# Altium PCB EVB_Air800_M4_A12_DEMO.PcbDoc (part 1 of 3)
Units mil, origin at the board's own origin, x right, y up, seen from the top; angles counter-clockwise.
Board outline 2106 x 2583.39 mil, 2 copper layers (Top, Bottom), stack 12.7 mil thick; 125 components, 94 nets, 414 pads, 454 vias.
Unrouted connection lines stored in the file: 290.
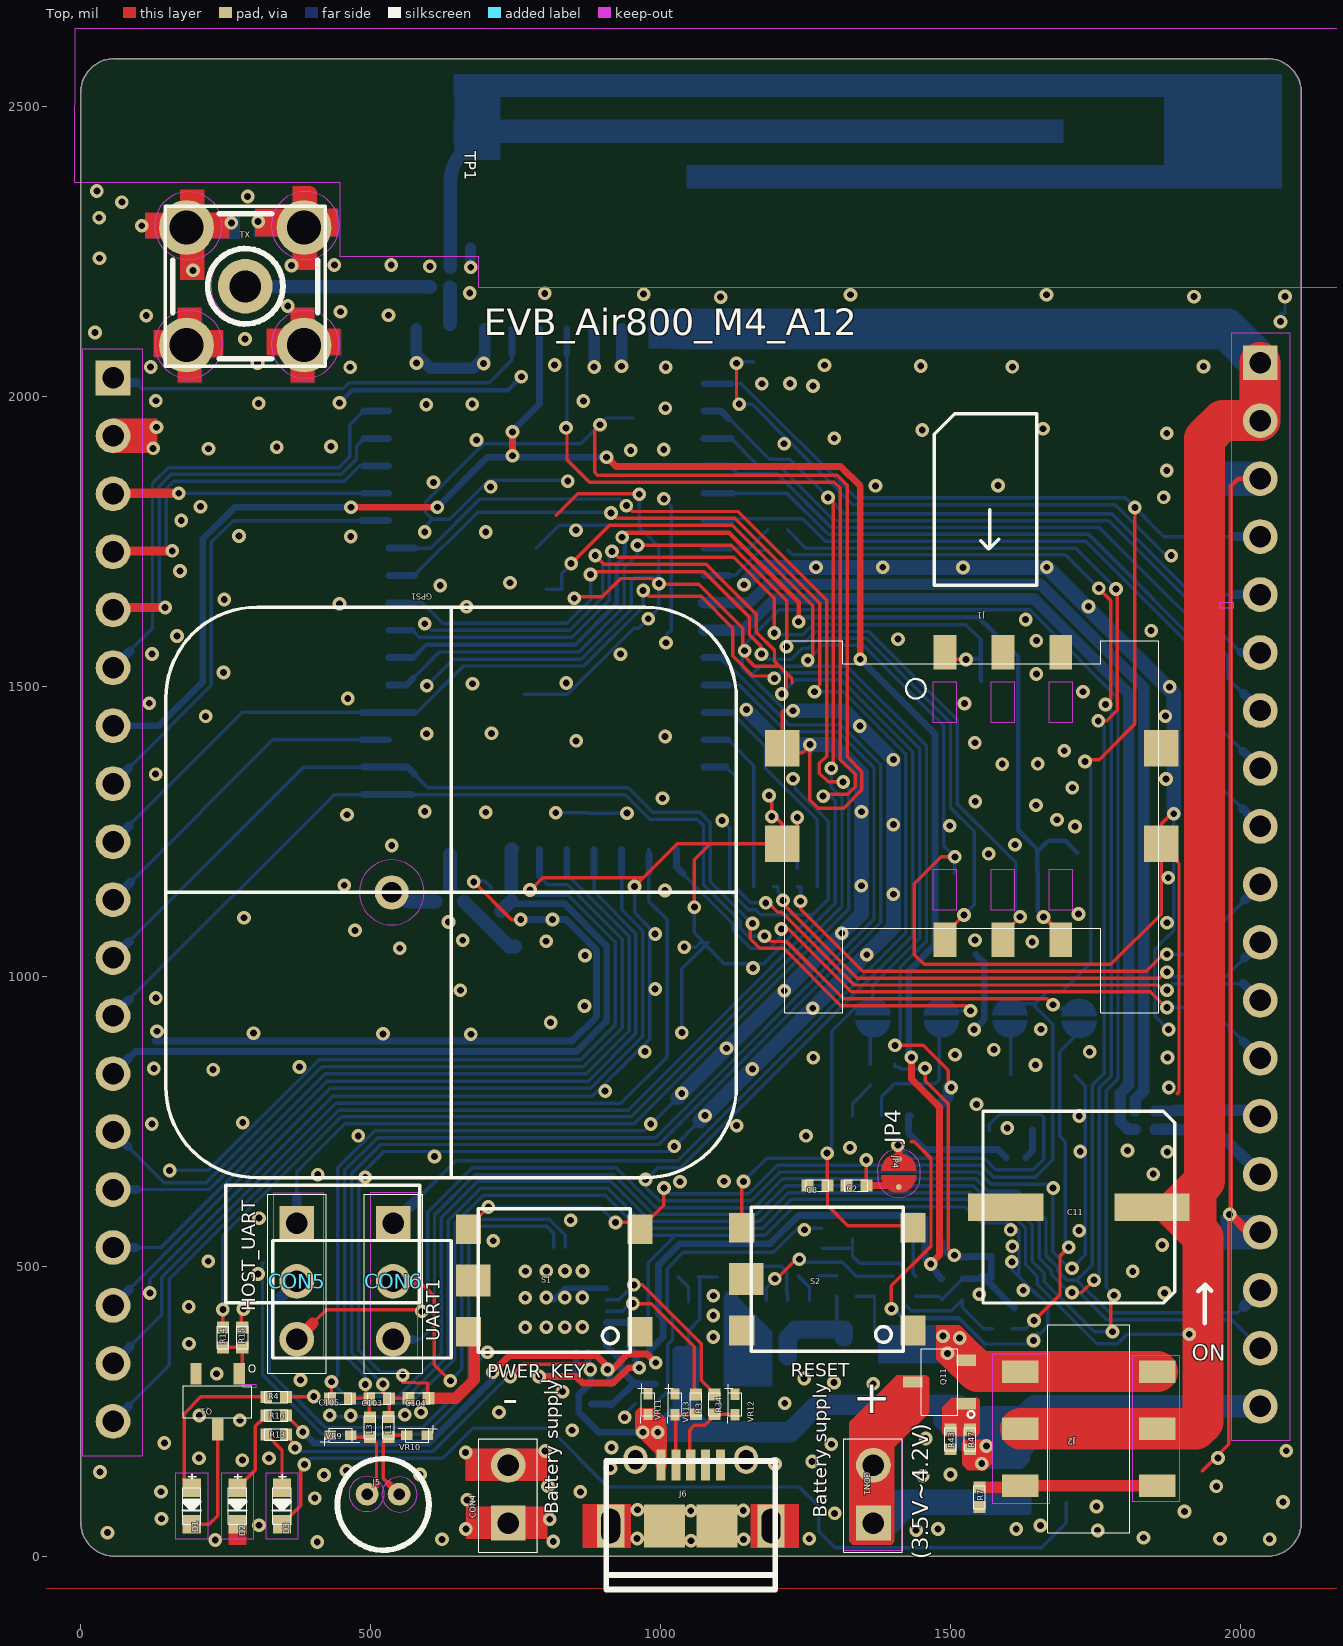
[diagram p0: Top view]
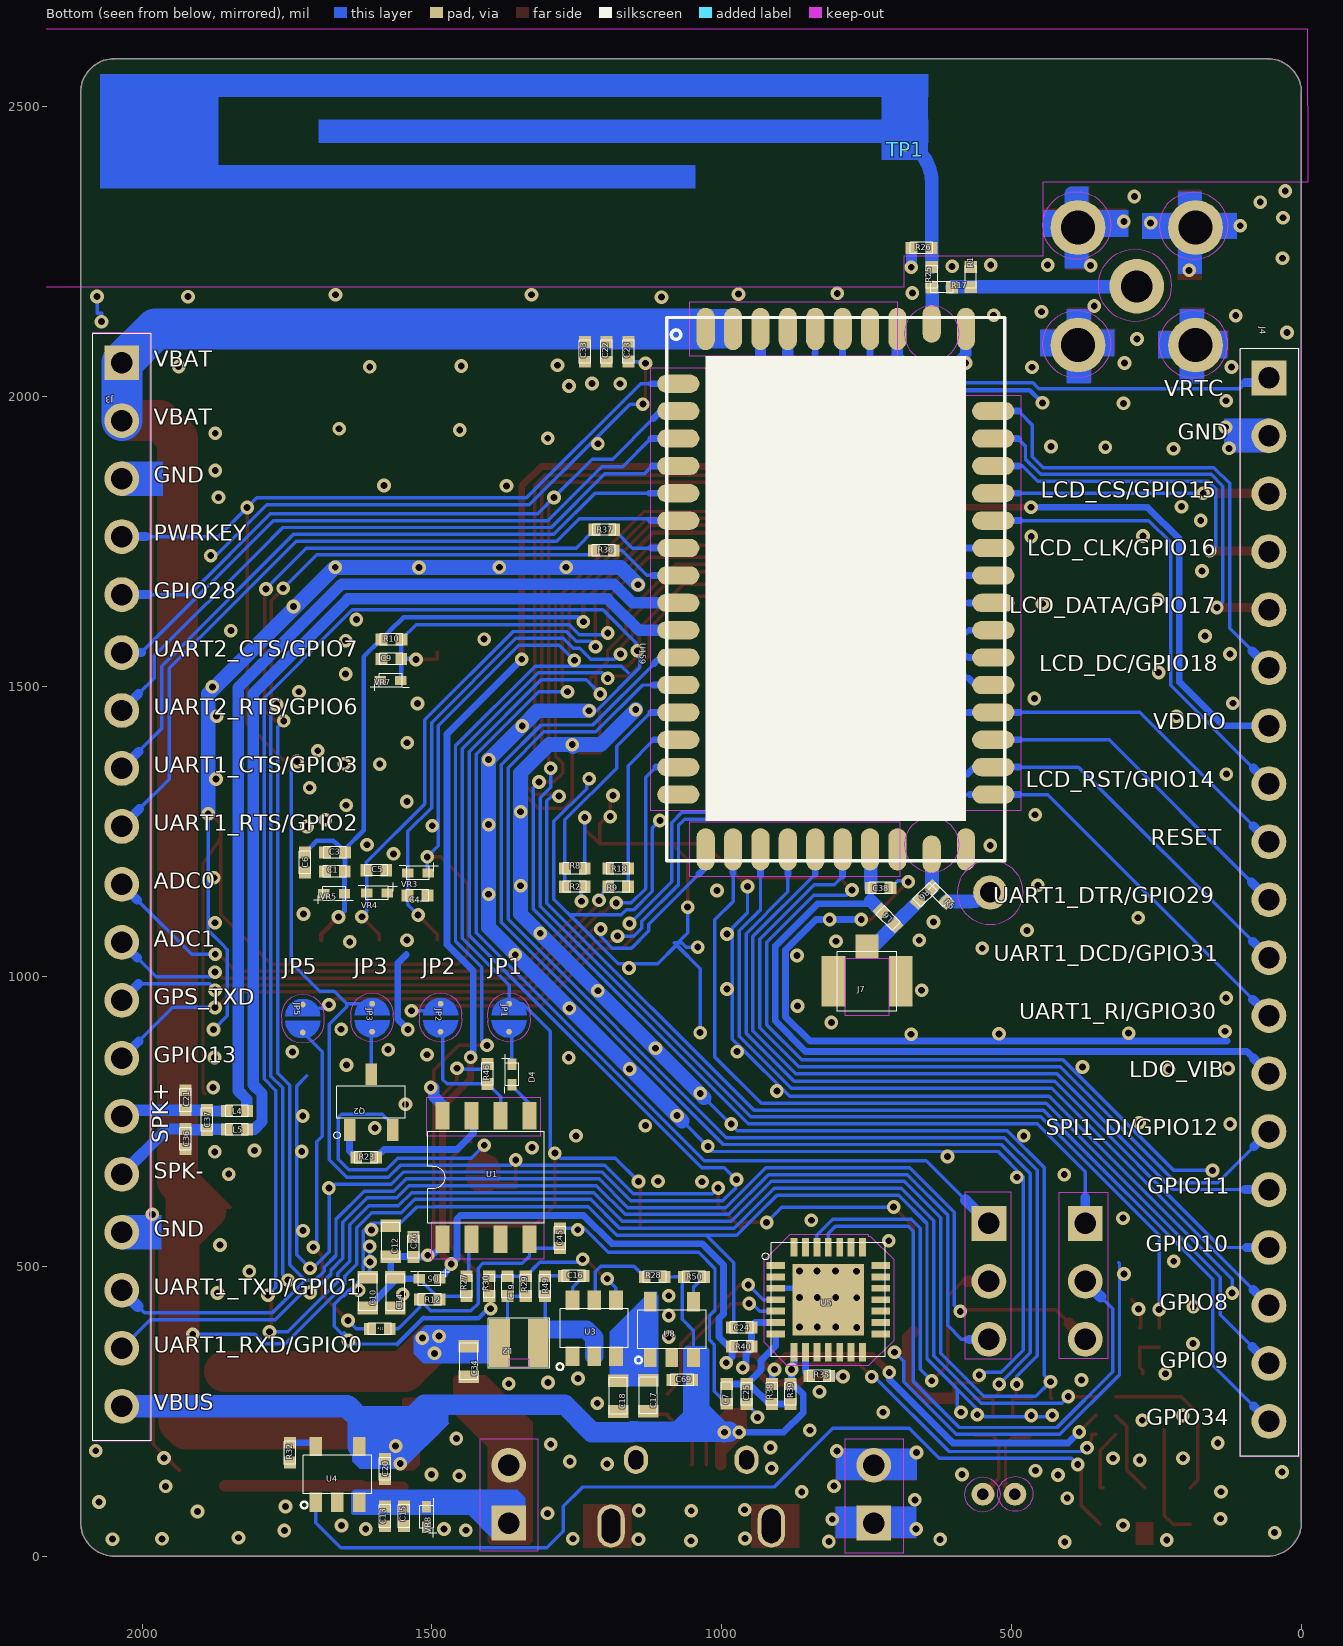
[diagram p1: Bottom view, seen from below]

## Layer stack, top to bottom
Solder Mask Top: solder mask 0.4, Solder Resist, Dk 3.5
Top: signal copper 1.35
Dielectric 1: dielectric 10, FR-4, Dk 4.3
Bottom: signal copper 1.35
Solder Mask Bottom: solder mask 0.4, Solder Resist, Dk 3.5

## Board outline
0.03,2524.27 cw(c59.08,2524.27) 59.08,2583.32 2046.97,2583.32 cw(c2046.97,2524.27) 2106.02,2524.27 2106.02,58.99 cw(c2046.97,58.99) 2046.97,-0.07 59.08,-0.07 cw(c59.08,58.99) 0.03,58.99

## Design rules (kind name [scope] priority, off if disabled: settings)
Clearance "Clearance - Default - DEFAULT- SMD" [IsVia vs IsSMTPin] p1: gap=1.97 ignorepadtopadclearanceinfootprint=FALSE
Clearance "Clearance - Default - DEFAULT - Via" [IsVia vs IsVia] p2: gap=0 ignorepadtopadclearanceinfootprint=FALSE
Clearance "Clearance - Default - DEFAULT - Net" [All] p3: gap=5.91 ignorepadtopadclearanceinfootprint=FALSE except(0: Arc-Hole Track-Hole SMDPad-Hole THPad-Hole Via-Hole Fill-Hole Poly-Hole Region-Hole Text-Hole; 10: Text-Text)
ComponentClearance "ComponentClearance - Default - DEFAULT" [All] p1: gap=0 collisioncheckmode=3 verticalgap=10 showdistances=FALSE
FanoutControl Fanout_Small [(CompPinCount < 5)] p3: bgadir=Out bgaviamode=Centered fanoutstyle=Auto fanoutdirection=OutThenIn viagrid=1 // Fanout_Small (Default Rule)
FanoutControl Fanout_SOIC [IsSOIC] p4: bgadir=Out bgaviamode=Centered fanoutstyle=Auto fanoutdirection=Alternating viagrid=1 // Fanout_SOIC (Default Rule)
HoleToHoleClearance "HoleToHoleClearance - Default - DEFAULT" [All] p1: gap=0 allowstackedmicrovias=TRUE
Length "Default Length" [All] p1: maxlimit=50000 minlimit=0
MaxMinImpedance "Default Impedance" [All] p1: minimum=50.00 maximum=150.0
ParallelSegment "Default Parallel Segment Adjasent" [All] p1: limit=1000 gap=200
ParallelSegment "Default Parallel Segment Same Layer" [All] p2: limit=1000 gap=200
PlaneConnect "Default PlaneConnect" [All] p1: planeconnectstyle=Relief reliefexpansion=20 reliefentries=0 reliefconductorwidth=15 reliefairgap=10
PolygonConnect "PolygonConnect - Default SMT" [IsSMTPin] p1: connectstyle=Direct reliefconductorwidth=11.81 reliefentries=4 polygonreliefangle="45 Angle" airgapwidth=10
PolygonConnect "PolygonConnect - Default Pad" [All] p2: connectstyle=Direct reliefconductorwidth=15 reliefentries=4 polygonreliefangle="45 Angle" airgapwidth=10
RoutingLayers "RoutingLayers - Default - DEFAULT" [All] p1: top layer_v5=TRUE bottom layer_v5=TRUE
RoutingPriority "RoutingPriority - Default - DEFAULT" [All] p1: routingpriority=3
RoutingTopology "Default Routing Topology" [All] p1: topology=Shortest
RoutingVias "RoutingVias - Default - DEFAULT" [All] p1: holewidth=11.81 width=23.62 viastyle="Through Hole" minholewidth=11.81 minwidth=23.62 maxholewidth=11.81 maxwidth=23.62
SMDToCorner "SMDToCorner - Default - DEFAULT" [All] p1: distance=0
SolderMaskExpansion [All] p1: expansion=4
Width "Default Width" [All] p1: maxlimit=118.11 minlimit=5.91 preferedwidth=5.91
22 further rules are at their usual default settings.

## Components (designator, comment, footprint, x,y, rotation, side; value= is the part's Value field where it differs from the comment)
C1 "SC0402" SC0402 1667.39,1181.32 r0 bottom
C2 "SC0402" SC0402 1338.32,639.23 r180 top
C3 "SC0402" SC0402 1667.02,1214.11 r0 bottom
C4 "SC0402" SC0402 1524.72,1139.78 r0 bottom
C5 "SC0402" SC0402 1595.74,1183.25 r0 bottom
C6 "SC0402" SC0402 1718.91,1196.66 r90 bottom
C7 "SC0402" SC0402 991.45,280.05 r270 bottom
C8 "SC0402" SC0402 1271.29,639.22 r180 top
C9 "SC0402" SC0402 1569.93,1547.89 r180 bottom
C10 "SC0603" SC0603 1610.24,454.72 r270 bottom
C11 "CAP-AL-1000UF-10.4X10.4" CAP-AL-1000UF-10.4X10.4 1722.06,602.14 r180 top
C12 "SC0603" SC0603 1570.87,543.31 r270 bottom
C13 "SC0402" SC0402 1581.12,68.82 r270 bottom
C14 "SC0603" SC0603 1562.99,454.72 r90 bottom
C15 "SC0402" SC0402 1548.01,68.91 r90 bottom
C16 "SC0402" SC0402 1255.39,483.52 r0 bottom
C17 "SC0603" SC0603 1126.84,276.84 r90 bottom
C18 "SC0603" SC0603 1178.72,276.12 r90 bottom
C19 "SC0402" SC0402 1369.57,465.8 r270 bottom
C20 "SC0402" SC0402 1580.86,150.33 r90 bottom
C21 "SC0402" SC0402 1924.69,786.67 r90 bottom
C22 "SC0402" SC0402 1198.68,2077.46 r90 bottom
C23 "SC0402" SC0402 1161.13,2077.72 r90 bottom
C24 "SC0402" SC0402 965.54,394.64 r180 bottom
C25 "SC0402" SC0402 956.95,279.82 r270 bottom
C26 "SC0402" SC0402 1531.5,533.46 r90 bottom
C33 "SC0402" SC0402 1236.14,2077.46 r90 bottom
C34 "SC0603" SC0603 1436.5,335.88 r90 bottom
C36 "SC0402" SC0402 1924.69,719.74 r90 bottom
C37 "SC0402" SC0402 1887.97,752.59 r90 bottom
C38 "SC0402" SC0402 725.98,1152.59 r180 bottom
C45 "SC0402" SC0402 1279.02,548.48 r270 bottom
C69 "SC0402" SC0402 1068.31,303.58 r180 bottom
C103 "SC0402" SC0402 515.01,272.15 r180 top
C104 "SC0402" SC0402 582.81,272.4 r180 top
C105 "SC0402" SC0402 447.73,272.35 r0 top
CON1 "DIP2X1-2.54" DIP2X1-2.54 1367.6,57.02 r90 top
CON4 "DIP2X1-2.54" DIP2X1-2.54 737.68,57.02 r90 top
CON5 "DIP3X1-2.54" DIP3X1-2.54 372.97,574.07 r270 top
CON6 "DIP3X1-2.54" DIP3X1-2.54 539.21,574.07 r270 top
D1 "LED-0603" LED-0603 191.97,86.56 r270 top
D2 "LED-0603" LED-0603 270.71,86.56 r270 top
D3 "LED-0603" LED-0603 347.48,86.56 r270 top
D4 "ESD-TVS-UM5079" ESD-TVS-UM5079 1361.98,830.86 r90 bottom
D5 "ESD-TVS-UM5079" ESD-TVS-UM5079 1504.09,478.48 r180 bottom
GPS1 "DAS1575R25C54" DAS1575R25C54 639.17,1144.93 r90 top
J1 "SIM-CAF99-06183-1503" SIM-CAF99-06183-1503 1537.36,1311.25 r90 top
J2 "SHW-SPDT" SHW-SPDT 1739.31,219.82 r90 top
J3 "DIP19X1-2.54" DIP19X1-2.54 2034.83,2058.77 r270 bottom
J4 "DIP19X1-2.54" DIP19X1-2.54 56.06,2032.48 r270 bottom
J5 "MIC_A5311" MIC_A5311 494.37,106.94 r0 top
J6 "USO170531D_A5311" USO170531D_A5311 1052.64,157.41 r0 top
J7 "RF-ANT-SOCKET-U.FL-R-SMT" RF-ANT-SOCKET-U.FL-R-SMT 749.34,991.56 r0 bottom
JP1 "R60L08" R60L08 1336.76,932.91 r90 bottom
JP2 "R60L08" R60L08 1454.87,932.91 r90 bottom
JP3 "R60L08" R60L08 1572.98,932.91 r90 bottom
JP4 "R60L08" R60L08 1381.38,656.75 r270 top
JP5 "R60L08" R60L08 1752.77,923.5 r270 bottom
L1 "SL0402" SL0402 531.09,222.69 r270 top
L2 "MRSC252A12-4R7W-N" MRSC252A12-4R7W-N 1349.88,367.38 r270 bottom
L3 "SL0402" SL0402 498.98,222.47 r270 top
L4 "SL0402" SL0402 1836.22,767.86 r180 bottom
L5 "SL0402" SL0402 1836.22,736.37 r180 bottom
L6 "SL0402" SL0402 713.17,1100.72 r45 bottom
Q1 "SOT-23(MMBT3904)" SOT-23(MMBT3904) 236.59,266.63 r90 top
Q2 "SOT-23(MMBT3904)" SOT-23(MMBT3904) 1604.63,783.25 r270 bottom
Q11 "SOT-23" SOT-23 1481.77,300.45 r90 top
R1 "SR0402" SR0402 570.44,2206.66 r270 bottom
R2 "SR0402" SR0402 1253.43,1154.78 r180 bottom
R3 "SR0402" SR0402 1061.73,261.87 r270 top
R4 "SR0402" SR0402 337.52,274.78 r0 top
R5 "SR0402" SR0402 624.86,1141.17 r225 bottom
R6 "SR0402" SR0402 649.4,1141.05 r315 bottom
R7 "SR0402" SR0402 1550.33,101.71 r90 top
R8 "SR0402" SR0402 1253.43,1186.27 r0 bottom
R9 "SR0402" SR0402 1178.62,1154.78 r0 bottom
R10 "SR0402" SR0402 1569.72,1581.3 r0 bottom
R11 "SR0402" SR0402 1589.71,391.98 r180 bottom
R12 "SR0402" SR0402 1503.85,442.49 r0 bottom
R13 "SR0402" SR0402 337.52,210.2 r0 top
R14 "SR0402" SR0402 245.55,377.22 r270 top
R15 "SR0402" SR0402 279.02,377.22 r270 top
R16 "SR0402" SR0402 337.52,242.48 r0 top
R17 "SR0402" SR0402 620.04,2188.78 r0 bottom
R18 "SR0402" SR0402 1178.62,1186.27 r180 bottom
R23 "SR0402" SR0402 1613.4,687.6 r0 bottom
R25 "SR0402" SR0402 637.69,2206.42 r90 bottom
R26 "SR0402" SR0402 655.55,2256.42 r180 bottom
R27 "SR0402" SR0402 1440.43,465.8 r90 bottom
R28 "SR0402" SR0402 1115.63,481.55 r0 bottom
R29 "SR0402" SR0402 1338.07,465.8 r270 bottom
R30 "SR0402" SR0402 1401.06,465.8 r90 bottom
R32 "SR0402" SR0402 1744.7,178.64 r270 bottom
R34 "SR0402" SR0402 1093.23,261.87 r270 top
R35 "SR0402" SR0402 832.03,311.11 r0 bottom
R36 "SR0402" SR0402 1203.33,1734.92 r180 bottom
R37 "SR0402" SR0402 1202.49,1770.5 r180 bottom
R38 "SR0402" SR0402 913.66,279.86 r270 bottom
R39 "SR0402-NF" SR0402-NF 881.64,279.84 r90 bottom
R40 "SR0402" SR0402 965.38,361.79 r180 bottom
R43 "SR0402" SR0402 1500.79,201.49 r270 top
R46 "SR0402" SR0402 1404.19,831.76 r270 bottom
R47 "SR0402" SR0402 1534.26,201.49 r270 top
R49 "SR0402" SR0402 1304.61,465.8 r90 bottom
R50 "SR0402" SR0402 1047.9,481.79 r180 bottom
S1 "IT-1157P" IT-1157P 817.09,475.59 r180 top
S2 "IT-1157P" IT-1157P 1288.19,477.76 r180 top
TP1 "ANT-02" ANT-02 684.54,2423.27 r270 top
TX "SMA-V" SMA-V 284.13,2190.51 r0 top
U1 "EM78P153B-SOP8" EM78P153B-SOP8 1406.58,653.31 r180 bottom
U3 "JW5033S" JW5033S 1219.96,392.97 r180 bottom
U4 "SOT-235" SOT-235 1662.87,141 r180 bottom
U5 "USB-DRIVER-CP2102" USB-DRIVER-CP2102 816.25,442.39 r180 bottom
U8 "SOT-235" SOT-235 1086.1,391 r180 bottom
U159 "AIR800" AIR800 1094.63,1199.59 r180 bottom
VR3 "ESD-TVS-UM5079" ESD-TVS-UM5079 1523.96,1178.51 r180 bottom
VR4 "ESD-TVS-UM5079" ESD-TVS-UM5079 1594.62,1143.93 r180 bottom
VR5 "ESD-TVS-UM5079" ESD-TVS-UM5079 1668.48,1142.7 r0 bottom
VR7 "ESD-TVS-UM5079" ESD-TVS-UM5079 1571.24,1510.44 r0 bottom
VR8 "ESD-TVS-UM5079" ESD-TVS-UM5079 1508.99,67.5 r270 bottom
VR9 "ESD-TVS-UM5079" ESD-TVS-UM5079 448.67,208.61 r180 top
VR10 "ESD-TVS-UM5079" ESD-TVS-UM5079 580.56,208.61 r0 top
VR11 "ESD-TVS-UM5079" ESD-TVS-UM5079 978.86,262.14 r90 top
VR12 "ESD-TVS-UM5079" ESD-TVS-UM5079 1128.66,261.87 r90 top
VR13 "ESD-TVS-UM5079" ESD-TVS-UM5079 1025.5,262.01 r90 top

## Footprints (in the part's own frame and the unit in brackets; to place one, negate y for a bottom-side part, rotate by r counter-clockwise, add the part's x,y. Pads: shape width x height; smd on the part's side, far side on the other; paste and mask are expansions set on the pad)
AIR800 [mm]
  oval 1.85x0.8 smd: 1(0.5,20.9) 2(0.5,19.7) 3(0.5,18.5) 4(0.5,17.3) 5(0.5,16.1) 6(0.5,14.9) 7(0.5,13.7) 8(0.5,12.5) 9(0.5,11.3) 10(0.5,10.1) 11(0.5,8.9) 12(0.5,7.7) 13(0.5,6.5) 14(0.5,5.3) 15(0.5,4.1) 16(0.5,2.9) 27(14.3,2.9) 28(14.3,4.1) 29(14.3,5.3) 30(14.3,6.5) 31(14.3,7.7) 32(14.3,8.9) 33(14.3,10.1) 34(14.3,11.3) 35(14.3,12.5) 36(14.3,13.7) 37(14.3,14.9) 38(14.3,16.1) 39(14.3,17.3) 40(14.3,18.5) 41(14.3,19.7)
  oval 0.8x1.85 smd: 17(1.7,0.5) 18(2.9,0.5) 19(4.1,0.5) 20(5.3,0.5) 21(6.5,0.5) 22(7.7,0.5) 23(8.9,0.5) 24(10.1,0.5) 26(13.1,0.5) 42(13.1,23.3) 44(10.1,23.3) 45(8.9,23.3) 46(7.7,23.3) 47(6.5,23.3) 48(5.3,23.3) 49(4.1,23.3) 50(2.9,23.3) 51(1.7,23.3)
  oval 0.8x1.65 smd: 25(11.6,0.28) 43(11.6,23.52)
  rect 1.5x1.5 smd: 52(3.6,4.4) 53(7.4,11.9) 54(3.6,19.4)
  Top keep-out region: -0.7,21.6 1.7,21.6 1.7,2.2 -0.7,2.2 -0.7,21.6
  Top keep-out region: 1,1.7 10.2,1.7 10.2,-0.7 1,-0.7 1,1.7
  Top keep-out region: 13.1,20.4 15.5,20.4 15.5,2.2 13.1,2.2 13.1,20.4
  Top keep-out region: 1,24.5 10.1,24.5 10.1,22.1 1,22.1 1,24.5
  Top keep-out region: 12.8,23.1 12.709,23.559 12.449,23.949 12.059,24.209 11.6,24.3 11.6,24.3 11.141,24.209 10.751,23.949 10.491,23.559 10.4,23.1 10.4,23.1 10.491,22.641 10.751,22.251 11.141,21.991 11.6,21.9 11.6,21.9 12.059,21.991 12.449,22.251 12.709,22.641 12.8,23.1
  Top keep-out region: 12.8,0.7 12.709,1.159 12.449,1.549 12.059,1.809 11.6,1.9 11.6,1.9 11.141,1.809 10.751,1.549 10.491,1.159 10.4,0.7 10.4,0.7 10.491,0.241 10.751,-0.149 11.141,-0.409 11.6,-0.5 11.6,-0.5 12.059,-0.409 12.449,-0.149 12.709,0.241 12.8,0.7
  silkscreen extent 0,0 14.8,23.8
ANT-02 [mm]
  round 0.2 smd far side: 1(-0.066,-0.021)
  Bottom region: -3.316,-1.002 -3.316,1 0.364,1 0.364,-1.002 -3.316,-1.002
  Bottom region: -0.386,-1.045 -1.386,-1.045 -1.386,25.676 -0.386,25.676 -0.386,-1.045
  Bottom region: -2.386,-1.037 -3.386,-1.037 -3.386,31.231 -2.386,31.231 -2.386,-1.037
  Bottom region: 1.614,9.176 0.614,9.176 0.614,32.107 1.614,32.107 1.614,9.176
  Bottom region: 1.614,30.084 -3.386,30.084 -3.386,35.252 1.614,35.252 1.614,30.084
CAP-AL-1000UF-10.4X10.4 [mm]
  rect 3.3x1.2 smd: 1(-3.2,0) 2(3.2,0)
  silkscreen extent -4.2,-4.2 4.2,4.2
DAS1575R25C54 [mm]
  round 1.5 hole 0.9: 1(0,2.6)
  Keep-Out Layer region: 1.421,2.6 1.313,3.144 1.005,3.605 0.544,3.913 0,4.021 0,4.021 -0.544,3.913 -1.005,3.605 -1.313,3.144 -1.421,2.6 -1.421,2.6 -1.313,2.056 -1.005,1.595 -0.544,1.287 0,1.179 0,1.179 0.544,1.287 1.005,1.595 1.313,2.056 1.421,2.6
  silkscreen extent -12.5,-12.5 12.5,12.5
DIP2X1-2.54 [mil]
  rect 60x60 hole 37: 1(0,0)
  round 60 hole 37: 2(100,0)
  silkscreen extent -50,-50 146,51
DIP3X1-2.54 [mil]
  rect 60x60 hole 37: 1(0,0)
  round 60 hole 37: 2(100,0) 3(200,0)
  silkscreen extent -50,-50 258,51
DIP19X1-2.54 [mil]
  rect 60x60 hole 37: 1(0,0)
  round 60 hole 37: 2(100,0) 3(200,0) 4(300,0) 5(400,0) 6(500,0) 7(600,0) 8(700,0) 9(800,0) 10(900,0) 11(1000,0) 12(1100,0) 13(1200,0) 14(1300,0) 15(1400,0) 16(1500,0) 17(1600,0) 18(1700,0) 19(1800,0)
  silkscreen extent -50,-50 1860,51
EM78P153B-SOP8 [mm]
  rect 0.6x1.2 smd: 1(-1.905,-2.7) 2(-0.635,-2.7) 3(0.635,-2.7) 4(1.905,-2.7) 5(1.905,2.7) 6(0.635,2.7) 7(-0.635,2.7) 8(-1.905,2.7)
  silkscreen extent -2.55,-2 2.55,2
ESD-TVS-UM5079 [mm]
  rect 0.5x0.4 smd: 1(-0.45,0) 2(0.45,0)
  silkscreen extent -0.83,-0.3 0.89,0.45
IT-1157P [mm]
  rect 1.1x1.3 smd: 1(-3.75,2.25) 2(3.75,2.25) 3(-3.75,-2.25) 4(3.75,-2.25)
  rect 1.5x1.4 smd: 5(3.55,0)
  silkscreen extent -3.32,-3.15 3.32,3.15
JW5033S [mm]
  rect 0.6x0.85 smd: 1(-0.95,-1.225) 2(0,-1.225) 3(0.95,-1.225) 4(0.95,1.225) 5(0,1.225) 6(-0.95,1.225)
  silkscreen extent -1.65,-1.83 1.5,0.85
LED-0603 [mm]
  rect 0.8x0.8 smd: 1(-0.8,0) 2(0.8,0)
  Top keep-out region: -1.45,0.7 1.45,0.7 1.45,-0.7 -1.45,-0.7 -1.45,0.7
  silkscreen extent -1.39,-0.41 0.8,0.4
MIC_A5311 [mm]
  round 1 hole 0.5: 1(0,0) 2(1.4,0)
  silkscreen extent -1.3,-2.45 2.71,1.56
MRSC252A12-4R7W-N [mm]
  rect 2.1x0.9 smd: 1(0,0.85) 2(0,-0.85)
  silkscreen extent -1.1,-1.35 1.1,1.35
R60L08 [mil]
  round 10 smd: 1(-28.22,30.19) 2(20,30)
  Top region: -8.22,-0.07 -16.05,0.96 -23.35,3.99 -29.62,8.79 -34.42,15.06 -37.45,22.36 -38.48,30.19 -37.45,38.02 -34.42,45.32 -29.62,51.59 -23.35,56.4 -16.05,59.42 -8.22,60.45 -8.22,60.19 -8.22,0.19
  Top region: 0,60.26 7.83,59.23 15.13,56.21 21.4,51.4 26.2,45.13 29.23,37.83 30.26,30 29.23,22.17 26.2,14.87 21.4,8.6 15.13,3.79 7.83,0.77 0,-0.26 0,0 0,60
  Top keep-out region: -10.09,66.26 1.97,66.49 2.61,66.58 12.01,65.34 20.77,61.71 28.3,55.93 34.07,48.41 37.7,39.64 38.94,30.24 37.7,20.84 34.07,12.07 28.3,4.55 20.77,-1.23 12.01,-4.86 2.61,-6.1 1.97,-6.01 1.98,-5.78 -10.12,-6.07 -19.39,-4.85 -28.16,-1.22 -35.68,4.55 -41.45,12.07 -45.08,20.84 -46.32,30.24 -45.08,39.64 -41.45,48.41 -35.68,55.93 -28.16,61.7 -19.39,65.33 -10.05,66.56 -10.09,66.26
RF-ANT-SOCKET-U.FL-R-SMT [mm]
  rect 1.05x2.2 smd: 1(-1.475,0) 3(1.475,0)
  rect 1x1.05 smd: 2(0,-1.525)
  Top keep-out region: -0.95,1.5 0.95,1.5 0.95,-1.003 -0.95,-1.003 -0.95,1.5
  silkscreen extent -1.3,-1.3 1.3,1.3
SC0402 [mm]
  rect 0.52x0.53 smd: 1(-0.435,0) 2(0.435,0)
  silkscreen extent -0.5,-0.25 0.5,0.25
SC0603 [mm]
  rect 0.551x0.899 smd: 1(-0.675,0) 2(0.675,0)
  silkscreen extent -0.8,-0.4 0.8,0.4
SHW-SPDT [mm]
  rect 1x1.6 smd: 1(0,3) 2(0,-3) 3(-2.5,3) 4(-2.5,-3) 5(2.5,3) 6(2.5,-3)
  silkscreen extent -4.55,-1.8 4.55,1.8
SIM-CAF99-06183-1503 [mm]
  rect 1.5x1 smd: 1(6.3,1.18) 2(6.3,-1.36) 3(6.3,-3.9) 4(-6.3,-3.9) 5(-6.3,-1.36) 6(-6.3,1.18)
  rect 1.6x1.5 smd: 7(-2.1,8.3) 8(2.1,8.3) 9(-2.1,-8.3) 10(2.1,-8.3)
  Top keep-out region: -5,1.68 -3.2,1.68 -3.2,0.68 -5,0.68 -5,1.68
  Top keep-out region: -5,-0.86 -3.2,-0.86 -3.2,-1.86 -5,-1.86 -5,-0.86
  Top keep-out region: -5,-3.4 -3.2,-3.4 -3.2,-4.4 -5,-4.4 -5,-3.4
  Top keep-out region: 3.2,1.68 5,1.68 5,0.68 3.2,0.68 3.2,1.68
  Top keep-out region: 3.2,-0.86 5,-0.86 5,-1.86 3.2,-1.86 3.2,-0.86
  Top keep-out region: 3.2,-3.4 5,-3.4 5,-4.4 3.2,-4.4 3.2,-3.4
  silkscreen extent -9.5,-8.2 16.74,8.2
SL0402 [mm]
  rect 0.52x0.53 smd: 1(-0.435,0) 2(0.435,0)
  silkscreen extent -0.5,-0.25 0.5,0.25
SMA-V [mm]
  round 2.4 hole 1.4: 1(0,0)
  round 2.4 hole 1.5: 2(-2.575,2.575) 3(2.575,2.575) 4(2.575,-2.575) 5(-2.575,-2.575)
  silkscreen extent -3.5,-3.5 3.5,3.5
SOT-23 [mm]
  rect 0.5x0.85 smd: 1(-0.95,-1.175) 2(0.95,-1.175) 3(0,1.175)
  silkscreen extent -1.57,-1.53 1.45,0.8
SOT-23(MMBT3904) [mm]
  rect 0.95x0.5 smd: 1(1.225,-0.95) 2(1.225,0.95) 3(-1.225,0)
  silkscreen extent -0.7,-1.65 1.6,1.5
SOT-235 [mm]
  rect 0.55x0.85 smd: 1(-0.95,-1.225) 2(0,-1.225) 3(0.95,-1.225) 4(0.95,1.225) 5(-0.95,1.225)
  silkscreen extent -1.61,-1.49 1.5,0.85
SR0402 [mm]
  rect 0.52x0.53 smd: 1(-0.435,0) 2(0.435,0)
  silkscreen extent -0.5,-0.25 0.5,0.25
SR0402-NF [mm]
  rect 0.52x0.53 smd: 1(-0.435,0) 2(0.435,0)
  silkscreen extent -0.5,-0.25 0.5,0.25
USB-DRIVER-CP2102 [mm]
  rect 0.8x0.3 smd: 1(-2.3,1.5) 2(-2.3,1) 3(-2.3,0.5) 4(-2.3,0) 5(-2.3,-0.5) 6(-2.3,-1) 7(-2.3,-1.5) 15(2.3,-1.5) 16(2.3,-1) 17(2.3,-0.5) 18(2.3,0) 19(2.3,0.5) 20(2.3,1) 21(2.3,1.5)
  rect 0.3x0.8 smd: 8(-1.5,-2.3) 9(-1,-2.3) 10(-0.5,-2.3) 11(0,-2.3) 12(0.5,-2.3) 13(1,-2.3) 14(1.5,-2.3) 22(1.5,2.3) 23(1,2.3) 24(0.5,2.3) 25(0,2.3) 26(-0.5,2.3) 27(-1,2.3) 28(-1.5,2.3)
  rrect0% 3.15x3.15 smd: 29(0,0)
  rrect0% 0.5x0.5 smd: 30(0,0)
  silkscreen extent -2.9,-2.5 2.5,2.5
USO170531D_A5311 [mm]
  rect 0.4x1.35 smd: 1(-1.3,0) 2(-0.65,0) 3(0,0) 4(0.65,0) 5(1.3,0)
  rect 1.2x1.9 / inner oval 1.2x1.9 / far side oval 1.2x1.9 hole 0.825 slot 1.5 at 90 deg: 6(-3.512,-2.675) 9(3.512,-2.675)
  rect 1.8x1.9 smd: 7(-1.15,-2.675) 8(1.15,-2.675)
  oval 1.05x1.25 hole 0.65 slot 0.85 at 90 deg: 10(-2.425,0.225) 11(2.425,0.225)
  Top region: -2.624,-3.625 -4.723,-3.625 -4.723,-1.726 -2.624,-1.726 -2.624,-3.625
  Top region: 2.624,-1.725 4.723,-1.725 4.723,-3.624 2.624,-3.624 2.624,-1.725
  silkscreen extent -3.7,-5.46 3.7,0.18

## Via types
v1: diameter 23.62, hole 11.81, Top to Bottom, 454 vias

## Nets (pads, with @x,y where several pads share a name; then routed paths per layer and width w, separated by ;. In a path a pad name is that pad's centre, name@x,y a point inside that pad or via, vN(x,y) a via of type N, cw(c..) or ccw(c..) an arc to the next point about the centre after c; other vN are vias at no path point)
$$$315: C16.1 U3.6 | length 50.2
  Bottom w5.91: C16.1@1238.27,483.52 1238.27,483.32 1257.36,464.23 U3.6@1257.36,441.19
$$$319: L2.1 R49.1 U3.2 | length 234.6
  Bottom w5.91: R49.1@1304.61,448.67 1304.61,391 1304.61,389.03 1316.42,377.22 L2.1@1316.42,367.38
  Bottom w31.5: U3.2@1219.96,344.74 1219.96,377.22 1233.74,391 1304.61,391 1316.42,391 L2.1@1316.42,377.22
$$$1059: C19.1 R29.1 R30.2 U3.4 | length 276.9
  Top w5.91: v1(1197.63,478.52) 1196.86,477.75 1198.56,476.05 1234.77,512.26 v1(1239.93,512.26)
  Bottom w5.91: U3.4@1182.56,441.19 1182.56,462.87 1196.92,477.23 1196.83,477.78 v1(1197.63,478.52) ; v1(1239.93,512.26) 1245.06,507.13 1313.87,507.13 1325.65,495.35 1337.6,482.93 R29.1@1338.07,482.93 C19.1@1369.57,482.93 R30.2@1401.06,482.93
$$$1131: C21.1 C37.2 J3.14 L4.1 | length 187.8
  Bottom w19.68: L4.1@1853.34,767.86 1887.97,767.86 C37.2@1887.97,769.54 ; C37.2@1887.97,769.71 C37.2@1887.97,769.54 ; J3.14@2034.83,758.77 2024.06,769.54 C21.1@1924.69,769.54 C37.2@1887.97,769.54
$$$1132: C36.2 C37.1 J3.15 L5.1 | length 215.7
  Bottom w19.68: L5.1@1853.34,736.37 1887.97,736.37 C37.1@1887.97,735.86 ; C37.1@1887.97,735.46 C37.1@1887.97,735.86 ; J3.15@2034.83,658.77 1956.73,736.86 C36.2@1924.69,736.86 1924.69,735.86 C37.1@1887.97,735.86
$$$1779: R32.1 U4.5 | length 51
  Bottom w11.81: U4.5@1700.28,189.23 1700.28,195.76 R32.1@1744.7,195.76
$$$1984: C45.2 R11.2 R12.2 U1.4 | length 434.7
  Bottom w5.91: C45.2@1279.02,531.35 U1.4@1331.58,531.35 ; U1.4@1331.58,547.01 U1.4@1331.58,531.35 ; R12.2@1520.98,442.49 R12.2@1520.98,442.3 ; R11.2@1572.59,391.98 1558.06,391.98 1520.98,429.07 R12.2@1520.98,442.3 ; U1.4@1331.58,531.35 1331.58,517.57 1343.98,505.17 1412.02,505.17 1420.35,496.83 1420.35,435.56 1432.72,423.19 1501.87,423.19 R12.2@1520.98,442.3
$$$3298: R1.2 R17.1 TX.1 | length 319.6
  Bottom w5.91: TX.1@284.13,2190.51 TX.1@320.46,2189.54
  Bottom w23.62: TX.1@320.46,2189.54 R1.2@570.44,2189.54 602.92,2189.54 R17.1@602.92,2188.78
$$$3324: R23.1 U1.7 | length 218.8
  Bottom w11.81: U1.7@1431.58,759.61 1428.14,759.61 1428.14,730.06 1456.96,701.25 1582.82,701.25 1596.27,687.79 R23.1@1596.27,687.6
$$$3343: Q2.1 R23.2 | length 52.2
  Bottom w11.81: R23.2@1630.52,687.6 1642.03,699.11 Q2.1@1642.03,735.02
$$$3383: JP3.1 Q2.3 | length 73.8
  Bottom w5.91: JP3.1@1603.17,904.69 1604.63,903.23 Q2.3@1604.63,831.48
$$$3814: D4.1 U1.5 | length 66.1
  Bottom w5.91: U1.5@1331.58,759.61 1331.58,780.76 1361.98,811.17 D4.1@1361.98,813.14
$$$5102: D4.2 JP1.1 | length 68.1
  Bottom w5.91: D4.2@1361.98,848.57 1361.98,909.66 JP1.1@1366.95,904.69
$$$8496: D1.1 R4.1 | length 287.1
  Top w5.91: D1.1@191.97,118.06 178.62,131.4 178.62,245.88 207.52,274.78 R4.1@320.39,274.78
$$$8691: Q1.1 R14.2 R15.2 | length 80.8
  Top w5.91: R14.2@245.55,360.09 R15.2@279.02,360.09 279.02,326.04 273.99,321.01 Q1.1@273.99,314.86
$$$8917: D2.1 R16.1 | length 145.7
  Top w5.91: D2.1@270.71,118.06 301.3,148.65 301.3,224.3 306.72,229.72 307.83,229.72 320.39,242.28 R16.1@320.39,242.48
$$$13463: R5.1 R6.1 U159.25 | length 58.3
  Bottom w23.62: R5.1@636.97,1153.28 637.07,1153.38 637.17,1153.48 637.23,1153.42 637.23,1210.62 U159.25@637.94,1210.62
$$$14662: R35.2 U5.9 | length 43.4
  Bottom w11.81: R35.2@849.16,311.11 855.62,317.58 U5.9@855.62,351.84
$$$17025: D1.2 Q1.3 | length 199.1
  Top w5.91: D1.2@191.97,55.07 221.52,55.07 236.59,70.13 Q1.3@236.59,218.4
$$$20594: R37.2 U159.7 | length 123.6
  Bottom w5.91: 1122.34,1738.96 1154.03,1738.96 1185.37,1770.3 R37.2@1185.37,1770.5
  Bottom w11.81: U159.7@1074.95,1738.96 1122.34,1738.96
$$$20596: R36.2 U159.8 | length 129.2
  Bottom w5.91: 1118.53,1691.72 1129.22,1691.72 1172.43,1734.92 R36.2@1186.21,1734.92
  Bottom w11.81: U159.8@1074.95,1691.72 1118.53,1691.72
$$$20923: D3.1 R13.1 | length 108.8
  Top w5.91: R13.1@320.39,210.2 320.39,210 347.48,182.91 D3.1@347.48,118.06 D3.1@342.01,118.06
$$$21291: R27.2 U1.2 | length 67.8
  Bottom w5.91: U1.2@1431.58,547.01 1436.5,542.09 1436.5,486.86 R27.2@1440.43,482.93
$$$22201: R25.2 R26.2 TP1.1 | length 231.7
  Bottom w5.91: R26.2@637.69,2253.66 637.69,2255.69 R26.2@638.43,2256.42
  Bottom w23.62: R25.2@637.69,2223.54 R26.2@637.69,2253.66 ; R26.2@637.69,2255.69 637.69,2368.73 cw(c716.88,2368.73) 660.89,2424.72 662.03,2425.87 TP1.1@683.73,2425.87
$$$23197: C10.2 C12.2 C14.2 C26.1 D5.1 R12.1 R27.1 R46.1 U1.1 | length 794.7
  Top w5.91: v1(1456.8,841.56) 1456.8,820.46 1496.54,780.72 1496.54,529.87 v1(1507.27,519.13)
  Bottom w5.91: R46.1@1404.19,848.88 1404.19,843.86 1411.19,843.86 1415.26,839.79 1456.8,839.79 v1(1456.8,841.56) ; R27.1@1440.43,448.67 1480.54,448.67 R12.1@1486.72,442.49 1486.72,443.4 D5.1@1521.81,478.48 ; v1@1501.38,516.34 1504.17,519.13 v1(1507.27,519.13)
  Bottom w11.81: U1.1@1481.58,547.01 1486.22,542.37 1486.22,531.5 1495.16,522.56 1503.85,522.56 v1(1507.27,519.13) ; v1@1501.38,516.34 C26.1@1531.5,516.34 1531.5,516.73 C12.2@1570.87,516.73 1570.87,481.3 C14.2@1562.99,481.3 ; D5.1@1521.81,478.48 1559.6,478.48 C14.2@1561.61,480.5 ; C14.2@1554.18,482.39 1559.72,482.39 C14.2@1561.61,480.5 ; C10.2@1610.24,428.15 1610.24,431.82 1607.06,431.82 1566.17,472.72 1566.17,477.62 1562.99,477.62 C14.2@1562.99,481.3 ; C14.2@1561.61,480.5 1562.41,481.3 C14.2@1562.99,481.3
$$$24126: J6.3 R34.2 VR12.1 | length 155.3
  Top w5.91: J6.3@1052.64,157.41 1050.55,157.41 1050.55,217.65 1058.54,225.64 1076.84,225.64 1094.49,243.29 1093.23,243.29 R34.2@1093.23,244.74 1128.07,244.74 VR12.1@1128.66,244.15
$$$24127: J6.2 R3.2 VR13.1 | length 123.6
  Top w5.91: VR13.1@1025.5,244.3 VR13.1@1027.05,244.3 ; J6.2@1027.05,157.41 VR13.1@1027.05,244.3 ; R3.2@1061.73,244.74 1061.73,244.3 VR13.1@1027.05,244.3
$$$24133: GPS1.1 R5.2 | length 80.7
  Bottom w23.62: GPS1.1@536.81,1144.93 540.49,1141.26 ccw(c569.61,1170.38) 569.61,1129.2 612.61,1129.2 R5.2@612.75,1129.06
$$$24493: J2.3 J2.4 R7.2 | length 309.6
  Top w19.68: R7.2@1550.33,118.84 1621.2,118.84 J2.3@1621.2,121.4 J2.4@1857.42,121.4
$$$25885: R17.2 R25.1 U159.43 | length 64.7
  Bottom w5.91: R17.2@637.17,2188.78 R25.1@637.69,2189.29
  Bottom w23.62: R17.2@637.17,2188.78 637.17,2125.58 U159.43@637.94,2125.58
$$$26573: C7.1 C25.1 R38.2 R39.1 U5.7 | length 237.5
  Bottom w11.81: R39.1@881.64,262.72 R38.2@913.66,262.74 913.66,260.57 916.03,260.57 954.58,299.12 C25.1@954.78,299.12 ; U5.7@906.81,383.34 906.81,363.6 932.56,337.85 932.56,321.33 C25.1@954.78,299.12 ; C7.1@991.45,297.18 991.45,296.95 C25.1@956.95,296.95 ; C25.1@954.78,299.12 C25.1@956.95,296.95 ; C25.1@954.78,299.12 956.95,299.12 C25.1@956.95,296.95
$$$27173: J5.2 L1.2 VR10.1 | length 148.2
  Top w5.91: 531.21,125.22 522.4,134.03 522.4,196.88 L1.2@531.09,205.56 531.09,208.61 VR10.1@562.85,208.61 ; J5.2@546.08,110.35 J5.2@549.49,106.94
  Top w11.81: 531.21,125.22 J5.2@546.08,110.35
$$$27179: J5.1 L3.2 VR9.1 | length 143.8
  Top w5.91: VR9.1@466.39,208.61 469.66,205.34 L3.2@498.98,205.34 510.56,193.75 510.56,123.14
  Top w11.81: J5.1@494.37,106.94 510.56,123.14
$$$27497: J7.2 L6.1 R6.2 | length 123.6
  Bottom w5.91: L6.1@699.21,1091.23 698.83,1090.85 L6.1@701.06,1088.61
  Bottom w23.62: R6.2@661.51,1128.94 699.21,1091.23 738.85,1051.6 J7.2@749.34,1051.6
$$$28334: C17.2 C18.2 U3.3 U8.1 U8.5 | length 235
  Bottom w5.91: U8.5@1123.5,439.23 U8.1@1123.5,342.77 1126.84,342.77 C17.2@1126.84,303.41 1178.01,303.41 C18.2@1178.72,302.7 1182.56,306.53 U3.3@1182.56,344.74
$$$29442: JP2.1 R46.2 U1.6 | length 228.7
  Bottom w5.91: U1.6@1381.58,759.61 1381.58,792.21 1403.99,814.63 R46.2@1404.19,814.63 1473.53,814.63 1481.1,822.2 1481.1,900.74 JP2.1@1485.06,904.69
$$$30680: C16.2 R49.2 | length 32.7
  Bottom w5.91: C16.2@1272.52,483.52 1304.61,483.52 R49.2@1304.61,482.93
$$$32127: Q11.1 R43.1 R47.1 | length 80.5
  Top w5.91: R43.1@1500.79,218.62 R47.1@1534.26,218.62 1534.26,237.92 1528.03,244.14 Q11.1@1528.03,263.04
$$$32214: JP5.2 R11.1 | length 586.2
  Top w5.91: v1(1644.67,406.39) 1689.48,451.19 1689.48,517.81 v1(1704.55,532.89)
  Bottom w5.91: R11.1@1606.84,391.98 1606.84,392.18 1630.46,392.18 v1(1644.67,406.39) ; v1(1704.55,532.89) 1698.39,539.06 1698.39,714.83 1689.03,724.19 1689.03,869.76 JP5.2@1722.77,903.5
$$$32500: R50.2 U8.4 | length 50
  Bottom w5.91: R50.2@1030.77,481.79 1030.77,481.59 1048.7,463.67 U8.4@1048.7,439.23
$$$32561: R28.2 U3.5 | length 147.6
  Bottom w5.91: R28.2@1132.76,481.55 1132.76,481.75 1151.35,500.34 1208.54,500.34 1218.33,490.55 1218.33,452.17 1219.96,450.54 U3.5@1219.96,441.19
ADC0: J3.10 R2.2 | length 943.6
  Top w5.91: v1(1242.04,1129.68) 1242.04,1116.18 1349.29,1008.94 1464.89,1008.94 1838.5,1008.94 1867.82,1038.26 v1(1873.79,1038.26)
  Bottom w5.91: R2.2@1236.3,1154.78 1242.04,1154.78 v1(1242.04,1129.68) ; v1(1873.79,1038.26) 1914.32,1038.26 2007.97,1131.9
  Bottom w15.75: 2007.97,1131.9 J3.10@2034.83,1158.77
ADC1: J3.11 R9.2 | length 949.1
  Top w5.91: v1(1211.72,1131.29) 1211.72,1125.18 1339.8,997.11 1860.49,997.11 1871.9,1008.53 v1(1874.07,1007.52)
  Bottom w5.91: R9.2@1195.75,1154.78 1203.03,1154.78 1203.03,1147.3 v1(1211.72,1131.29) ; v1(1874.07,1007.52) 1873.49,1006.94 1880.75,999.67 1975.73,999.67 2008.28,1032.22 ; J3.11@2026.61,1050.55 J3.11@2034.83,1058.77
  Bottom w15.75: 2008.28,1032.22 J3.11@2026.61,1050.55
BB_ADC0: R2.1 R8.2 U159.13 | length 409.6
  Bottom w5.91: 1122.53,1455.5 1181.13,1396.9 1181.13,1359.37 1270.55,1269.95 R8.2@1270.55,1186.27 R2.1@1270.55,1154.78
  Bottom w11.81: U159.13@1074.95,1455.5 1122.53,1455.5
BB_ADC1: R9.1 R18.2 U159.14 | length 314
  Bottom w5.91: 1117.05,1408.25 1161.5,1363.81 R9.1@1161.5,1154.78
  Bottom w11.81: U159.14@1074.95,1408.25 1117.05,1408.25
CHG_LED: D3.2 U4.1 | length 1621.9
  Top w5.91: D3.2@347.48,55.07 379.84,87.43 379.84,151.92 v1(386.06,158.14)
  Bottom w5.91: v1(386.06,158.14) 396.67,168.75 624.77,168.75 676.46,220.43 808.24,220.43 909.37,119.3 1239.91,119.3 1273.32,85.89 1273.32,43.35 1301.95,14.72 1657.06,14.72 1700.28,57.93 U4.1@1700.28,92.77
D+: R34.1 U5.4 | length 314.8
  Top w5.91: v1(954.4,468.04) 969.23,468.04 1070.71,366.55 1070.71,303.23 1093.99,279.95 1093.23,279.95 R34.1@1093.23,279
  Bottom w5.91: U5.4@906.81,442.39 906.81,442.18 928.54,442.18 v1(954.4,468.04)
D-: R3.1 U5.5 | length 271.7
  Top w5.91: v1(952.78,435.81) 984.09,435.81 1058.38,361.52 1058.38,282.35 R3.1@1061.73,279
  Bottom w5.91: U5.5@906.81,422.71 934.33,422.71 947.43,435.81 v1(952.78,435.81)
